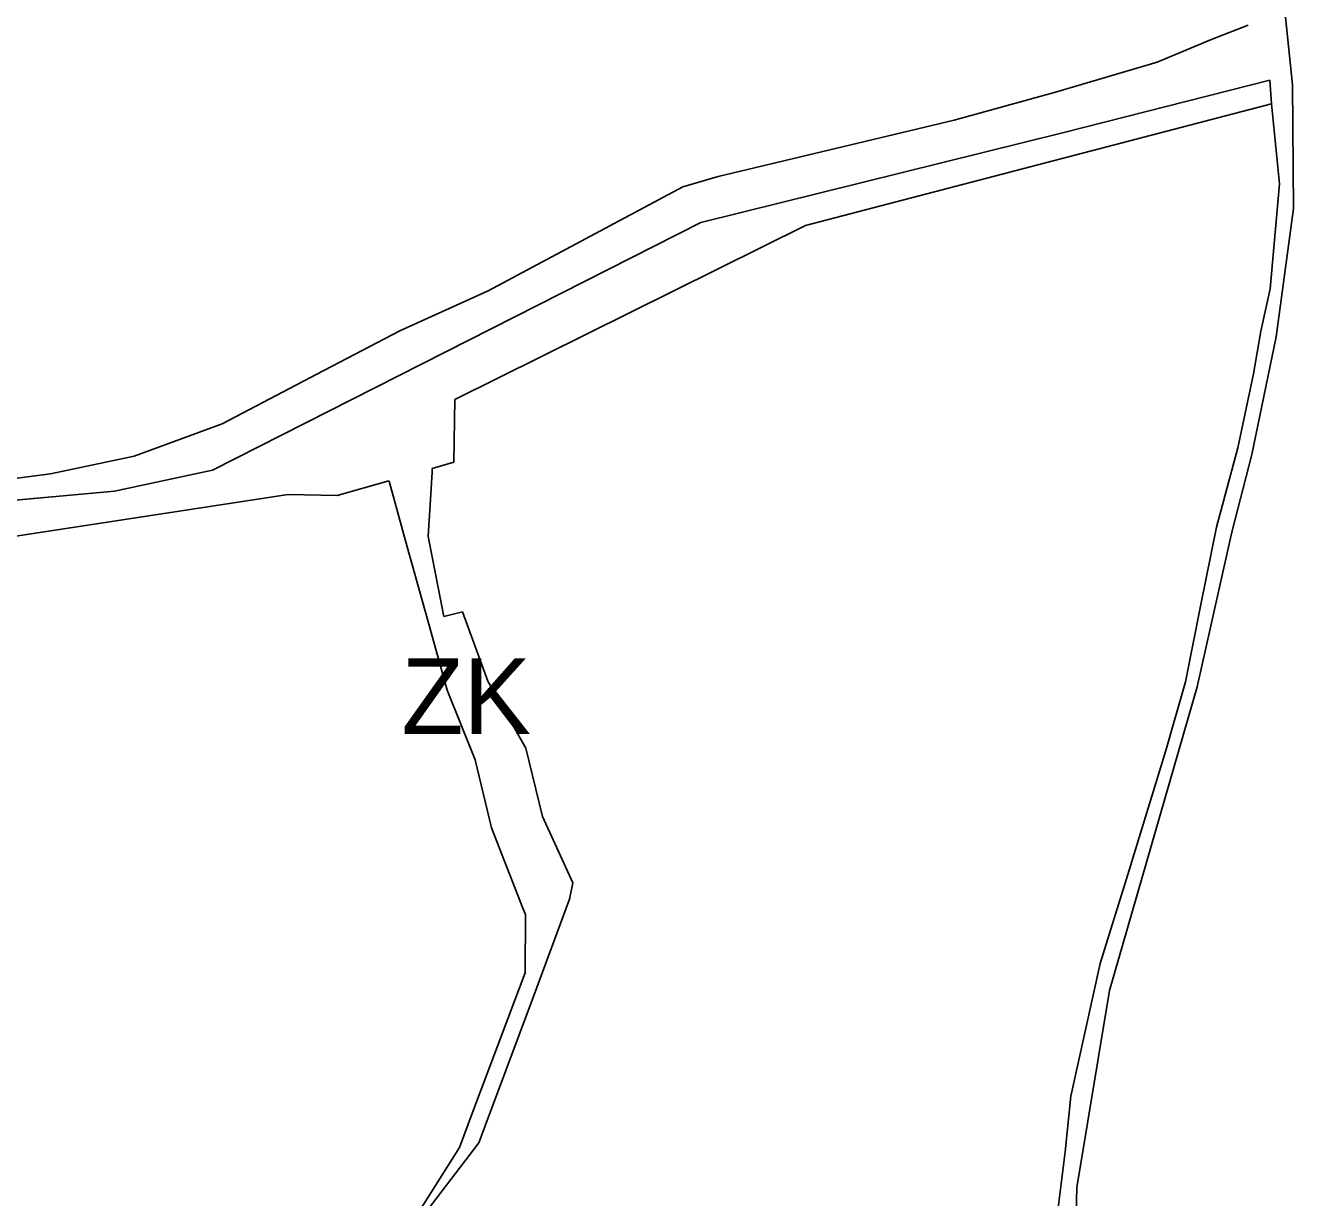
# Model space of a CAD drawing. Extents: x -555509 to -553005, y -1186756 to -1182560.
# Drawn here: x -553464 to -553229.6, y -1183479.6 to -1183263.1 of the extents above; entities that cross this region are included whole.
import ezdxf

# ---------------------------------------------------------------- set-up
doc = ezdxf.new("R2010")
doc.units = 0
for name, color, linetype in [('Level 26', 7, 'Continuous'), ('Level 59', 7, 'Continuous'), ('OBRYS_PLOCH', 7, 'Continuous'), ('stav_AP', 7, 'Continuous'), ('stav_ZK', 7, 'Continuous')]:
    doc.layers.add(name, color=color, linetype=linetype)

msp = doc.modelspace()

# ---------------------------------------------------------------- linework, layer by layer
at = {"layer": 'Level 26'}
for p, q in [((-553229.87, -1183274.06), (-553231.32, -1183259.77)), ((-553238.03, -1183263), (-553244.67, -1183265.61)), ((-553244.67, -1183265.61), (-553254.83, -1183269.88)), ((-553254.83, -1183269.88), (-553273.62, -1183275.38)), ((-553272.31, -1183282.89), (-553234.04, -1183273.16)), ((-553234.04, -1183273.16), (-553233.7, -1183277.58)), ((-553273.62, -1183275.38), (-553292.37, -1183280.56)), ((-553229.63, -1183296.92), (-553229.87, -1183274.06)), ((-553233.7, -1183277.58), (-553232.26, -1183292.33)), ((-553292.37, -1183280.56), (-553335.94, -1183290.96)), ((-553339.17, -1183299.49), (-553272.31, -1183282.89)), ((-553335.94, -1183290.96), (-553342.45, -1183292.9)), ((-553232.26, -1183292.33), (-553233.98, -1183311.73)), ((-553342.45, -1183292.9), (-553378.46, -1183312.07)), ((-553232.87, -1183320.6), (-553229.63, -1183296.92)), ((-553429.38, -1183345.21), (-553339.17, -1183299.49)), ((-553378.46, -1183312.07), (-553394.75, -1183319.48)), ((-553233.98, -1183311.73), (-553235.69, -1183319.53)), ((-553394.75, -1183319.48), (-553410.13, -1183327.48)), ((-553237.36, -1183342.31), (-553232.87, -1183320.6)), ((-553235.69, -1183319.53), (-553237.06, -1183327.42)), ((-553410.13, -1183327.48), (-553427.62, -1183336.66)), ((-553237.06, -1183327.42), (-553239.96, -1183341.09)), ((-553427.62, -1183336.66), (-553443.86, -1183342.66)), ((-553239.96, -1183341.09), (-553243.9, -1183355.75)), ((-553443.86, -1183342.66), (-553459.33, -1183345.89)), ((-553241.03, -1183356.66), (-553237.36, -1183342.31)), ((-553459.33, -1183345.89), (-553478.13, -1183348.4)), ((-553447.46, -1183349.1), (-553429.38, -1183345.21)), ((-553517.38, -1183355.42), (-553447.46, -1183349.1)), ((-553243.9, -1183355.75), (-553246.78, -1183370.01)), ((-553247.43, -1183385.26), (-553241.03, -1183356.66)), ((-553246.78, -1183370.01), (-553249.61, -1183384.33)), ((-553263.68, -1183441.33), (-553247.43, -1183385.26)), ((-553249.61, -1183384.33), (-553253.25, -1183397.01)), ((-553253.25, -1183397.01), (-553259.99, -1183419.13)), ((-553259.99, -1183419.13), (-553265.35, -1183436.32)), ((-553265.35, -1183436.32), (-553270.82, -1183460.83)), ((-553269.67, -1183477.71), (-553263.68, -1183441.33)), ((-553270.82, -1183460.83), (-553271.84, -1183471.16)), ((-553271.84, -1183471.16), (-553273.12, -1183481.48)), ((-553271.2, -1183528.31), (-553269.67, -1183477.71))]:
    msp.add_line(p, q, dxfattribs=at)
at = {"layer": 'OBRYS_PLOCH'}
for p, q in [((-553229.87, -1183274.06), (-553231.32, -1183259.77)), ((-553238.03, -1183263), (-553244.67, -1183265.61)), ((-553244.67, -1183265.61), (-553238.03, -1183263)), ((-553244.67, -1183265.61), (-553254.83, -1183269.88)), ((-553254.83, -1183269.88), (-553244.67, -1183265.61)), ((-553254.83, -1183269.88), (-553273.62, -1183275.38)), ((-553273.62, -1183275.38), (-553254.83, -1183269.88)), ((-553234.04, -1183273.16), (-553272.31, -1183282.89)), ((-553272.31, -1183282.89), (-553234.04, -1183273.16)), ((-553233.7, -1183277.58), (-553234.04, -1183273.16)), ((-553234.04, -1183273.16), (-553233.7, -1183277.58)), ((-553273.62, -1183275.38), (-553292.37, -1183280.56)), ((-553292.37, -1183280.56), (-553273.62, -1183275.38)), ((-553229.63, -1183296.92), (-553229.87, -1183274.06)), ((-553319.83, -1183300.03), (-553233.7, -1183277.58)), ((-553233.7, -1183277.58), (-553319.83, -1183300.03)), ((-553233.7, -1183277.58), (-553232.26, -1183292.33)), ((-553232.26, -1183292.33), (-553233.7, -1183277.58)), ((-553292.37, -1183280.56), (-553335.94, -1183290.96)), ((-553335.94, -1183290.96), (-553292.37, -1183280.56)), ((-553272.31, -1183282.89), (-553339.17, -1183299.49)), ((-553339.17, -1183299.49), (-553272.31, -1183282.89)), ((-553335.94, -1183290.96), (-553342.45, -1183292.9)), ((-553342.45, -1183292.9), (-553335.94, -1183290.96)), ((-553232.26, -1183292.33), (-553233.98, -1183311.73)), ((-553233.98, -1183311.73), (-553232.26, -1183292.33)), ((-553342.45, -1183292.9), (-553378.46, -1183312.07)), ((-553378.46, -1183312.07), (-553342.45, -1183292.9)), ((-553232.87, -1183320.6), (-553229.63, -1183296.92)), ((-553339.17, -1183299.49), (-553429.38, -1183345.21)), ((-553429.38, -1183345.21), (-553339.17, -1183299.49)), ((-553384.59, -1183332.16), (-553319.83, -1183300.03)), ((-553319.83, -1183300.03), (-553384.59, -1183332.16)), ((-553378.46, -1183312.07), (-553394.75, -1183319.48)), ((-553394.75, -1183319.48), (-553378.46, -1183312.07)), ((-553233.98, -1183311.73), (-553235.69, -1183319.53)), ((-553235.69, -1183319.53), (-553233.98, -1183311.73)), ((-553394.75, -1183319.48), (-553410.13, -1183327.48)), ((-553410.13, -1183327.48), (-553394.75, -1183319.48)), ((-553237.36, -1183342.31), (-553232.87, -1183320.6)), ((-553235.69, -1183319.53), (-553237.06, -1183327.42)), ((-553237.06, -1183327.42), (-553235.69, -1183319.53)), ((-553410.13, -1183327.48), (-553427.62, -1183336.66)), ((-553427.62, -1183336.66), (-553410.13, -1183327.48)), ((-553237.06, -1183327.42), (-553239.96, -1183341.09)), ((-553239.96, -1183341.09), (-553237.06, -1183327.42)), ((-553384.76, -1183343.75), (-553384.59, -1183332.16)), ((-553384.59, -1183332.16), (-553384.76, -1183343.75)), ((-553427.62, -1183336.66), (-553443.86, -1183342.66)), ((-553443.86, -1183342.66), (-553427.62, -1183336.66)), ((-553239.96, -1183341.09), (-553243.9, -1183355.75)), ((-553243.9, -1183355.75), (-553239.96, -1183341.09)), ((-553443.86, -1183342.66), (-553459.33, -1183345.89)), ((-553459.33, -1183345.89), (-553443.86, -1183342.66)), ((-553388.78, -1183344.9), (-553384.76, -1183343.75)), ((-553384.76, -1183343.75), (-553388.78, -1183344.9)), ((-553241.03, -1183356.66), (-553237.36, -1183342.31)), ((-553459.33, -1183345.89), (-553478.13, -1183348.4)), ((-553478.13, -1183348.4), (-553459.33, -1183345.89)), ((-553429.38, -1183345.21), (-553447.46, -1183349.1)), ((-553447.46, -1183349.1), (-553429.38, -1183345.21)), ((-553389.18, -1183351.63), (-553388.82, -1183345.6)), ((-553388.82, -1183345.6), (-553389.18, -1183351.63)), ((-553388.82, -1183345.6), (-553388.78, -1183344.9)), ((-553388.78, -1183344.9), (-553388.82, -1183345.6)), ((-553406.32, -1183349.92), (-553396.78, -1183347.19)), ((-553396.78, -1183347.19), (-553406.32, -1183349.92)), ((-553396.78, -1183347.19), (-553396.69, -1183347.53)), ((-553396.69, -1183347.53), (-553396.78, -1183347.19)), ((-553396.69, -1183347.53), (-553395.15, -1183353.08)), ((-553395.15, -1183353.08), (-553396.69, -1183347.53)), ((-553517.38, -1183355.42), (-553447.46, -1183349.1)), ((-553395.15, -1183353.08), (-553393.4, -1183359.38)), ((-553393.4, -1183359.38), (-553395.15, -1183353.08)), ((-553389.53, -1183357.41), (-553389.18, -1183351.63)), ((-553389.18, -1183351.63), (-553389.53, -1183357.41)), ((-553243.9, -1183355.75), (-553246.78, -1183370.01)), ((-553246.78, -1183370.01), (-553243.9, -1183355.75)), ((-553389.33, -1183358.42), (-553389.53, -1183357.41)), ((-553389.53, -1183357.41), (-553389.33, -1183358.42)), ((-553247.43, -1183385.26), (-553241.03, -1183356.66)), ((-553393.4, -1183359.38), (-553389.62, -1183372.99)), ((-553389.62, -1183372.99), (-553393.4, -1183359.38)), ((-553386.61, -1183372.25), (-553389.33, -1183358.42)), ((-553389.33, -1183358.42), (-553386.61, -1183372.25)), ((-553383.21, -1183371.41), (-553386.61, -1183372.25)), ((-553386.61, -1183372.25), (-553383.21, -1183371.41)), ((-553378.52, -1183384.22), (-553383.21, -1183371.41)), ((-553383.21, -1183371.41), (-553378.52, -1183384.22)), ((-553246.78, -1183370.01), (-553249.61, -1183384.33)), ((-553249.61, -1183384.33), (-553246.78, -1183370.01)), ((-553389.62, -1183372.99), (-553386.01, -1183385.87)), ((-553386.01, -1183385.87), (-553389.62, -1183372.99)), ((-553386.01, -1183385.87), (-553380.85, -1183398.75)), ((-553380.85, -1183398.75), (-553386.01, -1183385.87)), ((-553371.47, -1183396.58), (-553378.52, -1183384.22)), ((-553378.52, -1183384.22), (-553371.47, -1183396.58)), ((-553263.68, -1183441.33), (-553247.43, -1183385.26)), ((-553249.61, -1183384.33), (-553253.25, -1183397.01)), ((-553253.25, -1183397.01), (-553249.61, -1183384.33)), ((-553368.42, -1183409.2), (-553371.47, -1183396.58)), ((-553371.47, -1183396.58), (-553368.42, -1183409.2)), ((-553253.25, -1183397.01), (-553259.99, -1183419.13)), ((-553259.99, -1183419.13), (-553253.25, -1183397.01)), ((-553380.85, -1183398.75), (-553377.85, -1183411.3)), ((-553377.85, -1183411.3), (-553380.85, -1183398.75)), ((-553364.42, -1183417.96), (-553368.42, -1183409.2)), ((-553368.42, -1183409.2), (-553364.42, -1183417.96)), ((-553377.85, -1183411.3), (-553372.02, -1183426.12)), ((-553372.02, -1183426.12), (-553377.85, -1183411.3)), ((-553362.82, -1183421.45), (-553364.42, -1183417.96)), ((-553364.42, -1183417.96), (-553362.82, -1183421.45)), ((-553259.99, -1183419.13), (-553265.35, -1183436.32)), ((-553265.35, -1183436.32), (-553259.99, -1183419.13)), ((-553363.4, -1183424.45), (-553362.82, -1183421.45)), ((-553362.82, -1183421.45), (-553363.4, -1183424.45)), ((-553372.02, -1183426.12), (-553371.56, -1183427.27)), ((-553371.56, -1183427.27), (-553372.02, -1183426.12)), ((-553370.09, -1183442.42), (-553363.4, -1183424.45)), ((-553363.4, -1183424.45), (-553370.09, -1183442.42)), ((-553371.56, -1183427.27), (-553371.58, -1183438.09)), ((-553371.58, -1183438.09), (-553371.56, -1183427.27)), ((-553265.35, -1183436.32), (-553270.82, -1183460.83)), ((-553270.82, -1183460.83), (-553265.35, -1183436.32)), ((-553371.58, -1183438.09), (-553373.49, -1183443.15)), ((-553373.49, -1183443.15), (-553371.58, -1183438.09)), ((-553377.82, -1183463.17), (-553370.09, -1183442.42)), ((-553370.09, -1183442.42), (-553377.82, -1183463.17)), ((-553269.67, -1183477.71), (-553263.68, -1183441.33)), ((-553373.49, -1183443.15), (-553381.32, -1183463.89)), ((-553381.32, -1183463.89), (-553373.49, -1183443.15)), ((-553270.82, -1183460.83), (-553271.84, -1183471.16)), ((-553271.84, -1183471.16), (-553270.82, -1183460.83)), ((-553380.16, -1183469.46), (-553377.82, -1183463.17)), ((-553377.82, -1183463.17), (-553380.16, -1183469.46)), ((-553381.32, -1183463.89), (-553383.76, -1183470.34)), ((-553383.76, -1183470.34), (-553381.32, -1183463.89)), ((-553383.76, -1183470.34), (-553392.58, -1183484.35)), ((-553392.58, -1183484.35), (-553383.76, -1183470.34)), ((-553391.32, -1183484.04), (-553380.16, -1183469.46)), ((-553380.16, -1183469.46), (-553391.32, -1183484.04)), ((-553271.84, -1183471.16), (-553273.12, -1183481.48)), ((-553273.12, -1183481.48), (-553271.84, -1183471.16)), ((-553271.2, -1183528.31), (-553269.67, -1183477.71))]:
    msp.add_line(p, q, dxfattribs=at)
for points in [[(-553447.46, -1183349.1), (-553517.38, -1183355.42), (-553538.74, -1183358.44), (-553538.38, -1183365.99), (-553465.73, -1183357.42), (-553415.38, -1183349.71), (-553406.32, -1183349.92)], [(-553406.32, -1183349.92), (-553415.38, -1183349.71), (-553465.73, -1183357.42), (-553538.38, -1183365.99)]]:
    msp.add_lwpolyline(points, dxfattribs=at)
at = {"layer": 'stav_AP'}
for p, q in [((-553244.67, -1183265.61), (-553238.03, -1183263)), ((-553254.83, -1183269.88), (-553244.67, -1183265.61)), ((-553273.62, -1183275.38), (-553254.83, -1183269.88)), ((-553292.37, -1183280.56), (-553273.62, -1183275.38)), ((-553233.7, -1183277.58), (-553319.83, -1183300.03)), ((-553232.26, -1183292.33), (-553233.7, -1183277.58)), ((-553335.94, -1183290.96), (-553292.37, -1183280.56)), ((-553342.45, -1183292.9), (-553335.94, -1183290.96)), ((-553233.98, -1183311.73), (-553232.26, -1183292.33)), ((-553378.46, -1183312.07), (-553342.45, -1183292.9)), ((-553319.83, -1183300.03), (-553384.59, -1183332.16)), ((-553394.75, -1183319.48), (-553378.46, -1183312.07)), ((-553235.69, -1183319.53), (-553233.98, -1183311.73)), ((-553410.13, -1183327.48), (-553394.75, -1183319.48)), ((-553237.06, -1183327.42), (-553235.69, -1183319.53)), ((-553427.62, -1183336.66), (-553410.13, -1183327.48)), ((-553239.96, -1183341.09), (-553237.06, -1183327.42)), ((-553384.59, -1183332.16), (-553384.76, -1183343.75)), ((-553443.86, -1183342.66), (-553427.62, -1183336.66)), ((-553243.9, -1183355.75), (-553239.96, -1183341.09)), ((-553459.33, -1183345.89), (-553443.86, -1183342.66)), ((-553384.76, -1183343.75), (-553388.78, -1183344.9)), ((-553478.13, -1183348.4), (-553459.33, -1183345.89)), ((-553388.82, -1183345.6), (-553389.18, -1183351.63)), ((-553388.78, -1183344.9), (-553388.82, -1183345.6)), ((-553396.78, -1183347.19), (-553406.32, -1183349.92)), ((-553396.69, -1183347.53), (-553396.78, -1183347.19)), ((-553395.15, -1183353.08), (-553396.69, -1183347.53)), ((-553393.4, -1183359.38), (-553395.15, -1183353.08)), ((-553389.18, -1183351.63), (-553389.53, -1183357.41)), ((-553246.78, -1183370.01), (-553243.9, -1183355.75)), ((-553389.53, -1183357.41), (-553389.33, -1183358.42)), ((-553389.62, -1183372.99), (-553393.4, -1183359.38)), ((-553389.33, -1183358.42), (-553386.61, -1183372.25)), ((-553386.61, -1183372.25), (-553383.21, -1183371.41)), ((-553383.21, -1183371.41), (-553378.52, -1183384.22)), ((-553249.61, -1183384.33), (-553246.78, -1183370.01)), ((-553386.01, -1183385.87), (-553389.62, -1183372.99)), ((-553380.85, -1183398.75), (-553386.01, -1183385.87)), ((-553378.52, -1183384.22), (-553371.47, -1183396.58)), ((-553253.25, -1183397.01), (-553249.61, -1183384.33)), ((-553371.47, -1183396.58), (-553368.42, -1183409.2)), ((-553259.99, -1183419.13), (-553253.25, -1183397.01)), ((-553377.85, -1183411.3), (-553380.85, -1183398.75)), ((-553368.42, -1183409.2), (-553364.42, -1183417.96)), ((-553372.02, -1183426.12), (-553377.85, -1183411.3)), ((-553364.42, -1183417.96), (-553362.82, -1183421.45)), ((-553265.35, -1183436.32), (-553259.99, -1183419.13)), ((-553362.82, -1183421.45), (-553363.4, -1183424.45)), ((-553371.56, -1183427.27), (-553372.02, -1183426.12)), ((-553363.4, -1183424.45), (-553370.09, -1183442.42)), ((-553371.58, -1183438.09), (-553371.56, -1183427.27)), ((-553270.82, -1183460.83), (-553265.35, -1183436.32)), ((-553373.49, -1183443.15), (-553371.58, -1183438.09)), ((-553370.09, -1183442.42), (-553377.82, -1183463.17)), ((-553381.32, -1183463.89), (-553373.49, -1183443.15)), ((-553271.84, -1183471.16), (-553270.82, -1183460.83)), ((-553377.82, -1183463.17), (-553380.16, -1183469.46)), ((-553383.76, -1183470.34), (-553381.32, -1183463.89)), ((-553392.58, -1183484.35), (-553383.76, -1183470.34)), ((-553380.16, -1183469.46), (-553391.32, -1183484.04)), ((-553273.12, -1183481.48), (-553271.84, -1183471.16))]:
    msp.add_line(p, q, dxfattribs=at)
msp.add_lwpolyline([(-553406.32, -1183349.92), (-553415.38, -1183349.71), (-553465.73, -1183357.42), (-553538.38, -1183365.99)], dxfattribs=at)
at = {"layer": 'stav_ZK'}
for p, q in [((-553234.04, -1183273.16), (-553272.31, -1183282.89)), ((-553233.7, -1183277.58), (-553234.04, -1183273.16)), ((-553319.83, -1183300.03), (-553233.7, -1183277.58)), ((-553272.31, -1183282.89), (-553339.17, -1183299.49)), ((-553339.17, -1183299.49), (-553429.38, -1183345.21)), ((-553384.59, -1183332.16), (-553319.83, -1183300.03)), ((-553384.76, -1183343.75), (-553384.59, -1183332.16)), ((-553388.78, -1183344.9), (-553384.76, -1183343.75)), ((-553429.38, -1183345.21), (-553447.46, -1183349.1)), ((-553389.18, -1183351.63), (-553388.82, -1183345.6)), ((-553388.82, -1183345.6), (-553388.78, -1183344.9)), ((-553406.32, -1183349.92), (-553396.78, -1183347.19)), ((-553396.78, -1183347.19), (-553396.69, -1183347.53)), ((-553396.69, -1183347.53), (-553395.15, -1183353.08)), ((-553395.15, -1183353.08), (-553393.4, -1183359.38)), ((-553389.53, -1183357.41), (-553389.18, -1183351.63)), ((-553389.33, -1183358.42), (-553389.53, -1183357.41)), ((-553393.4, -1183359.38), (-553389.62, -1183372.99)), ((-553386.61, -1183372.25), (-553389.33, -1183358.42)), ((-553383.21, -1183371.41), (-553386.61, -1183372.25)), ((-553378.52, -1183384.22), (-553383.21, -1183371.41)), ((-553389.62, -1183372.99), (-553386.01, -1183385.87)), ((-553386.01, -1183385.87), (-553380.85, -1183398.75)), ((-553371.47, -1183396.58), (-553378.52, -1183384.22)), ((-553368.42, -1183409.2), (-553371.47, -1183396.58)), ((-553380.85, -1183398.75), (-553377.85, -1183411.3)), ((-553364.42, -1183417.96), (-553368.42, -1183409.2)), ((-553377.85, -1183411.3), (-553372.02, -1183426.12)), ((-553362.82, -1183421.45), (-553364.42, -1183417.96)), ((-553363.4, -1183424.45), (-553362.82, -1183421.45)), ((-553372.02, -1183426.12), (-553371.56, -1183427.27)), ((-553370.09, -1183442.42), (-553363.4, -1183424.45)), ((-553371.56, -1183427.27), (-553371.58, -1183438.09)), ((-553371.58, -1183438.09), (-553373.49, -1183443.15)), ((-553377.82, -1183463.17), (-553370.09, -1183442.42)), ((-553373.49, -1183443.15), (-553381.32, -1183463.89)), ((-553380.16, -1183469.46), (-553377.82, -1183463.17)), ((-553381.32, -1183463.89), (-553383.76, -1183470.34)), ((-553383.76, -1183470.34), (-553392.58, -1183484.35)), ((-553391.32, -1183484.04), (-553380.16, -1183469.46))]:
    msp.add_line(p, q, dxfattribs=at)
msp.add_lwpolyline([(-553447.46, -1183349.1), (-553517.38, -1183355.42), (-553538.74, -1183358.44), (-553538.38, -1183365.99), (-553465.73, -1183357.42), (-553415.38, -1183349.71), (-553406.32, -1183349.92)], dxfattribs=at)

# ---------------------------------------------------------------- texts
at = {"layer": 'Level 59'}
msp.add_text('ZK', height=14, dxfattribs=at).set_placement((-553394.45, -1183393.97))

doc.saveas('drawing.dxf')
